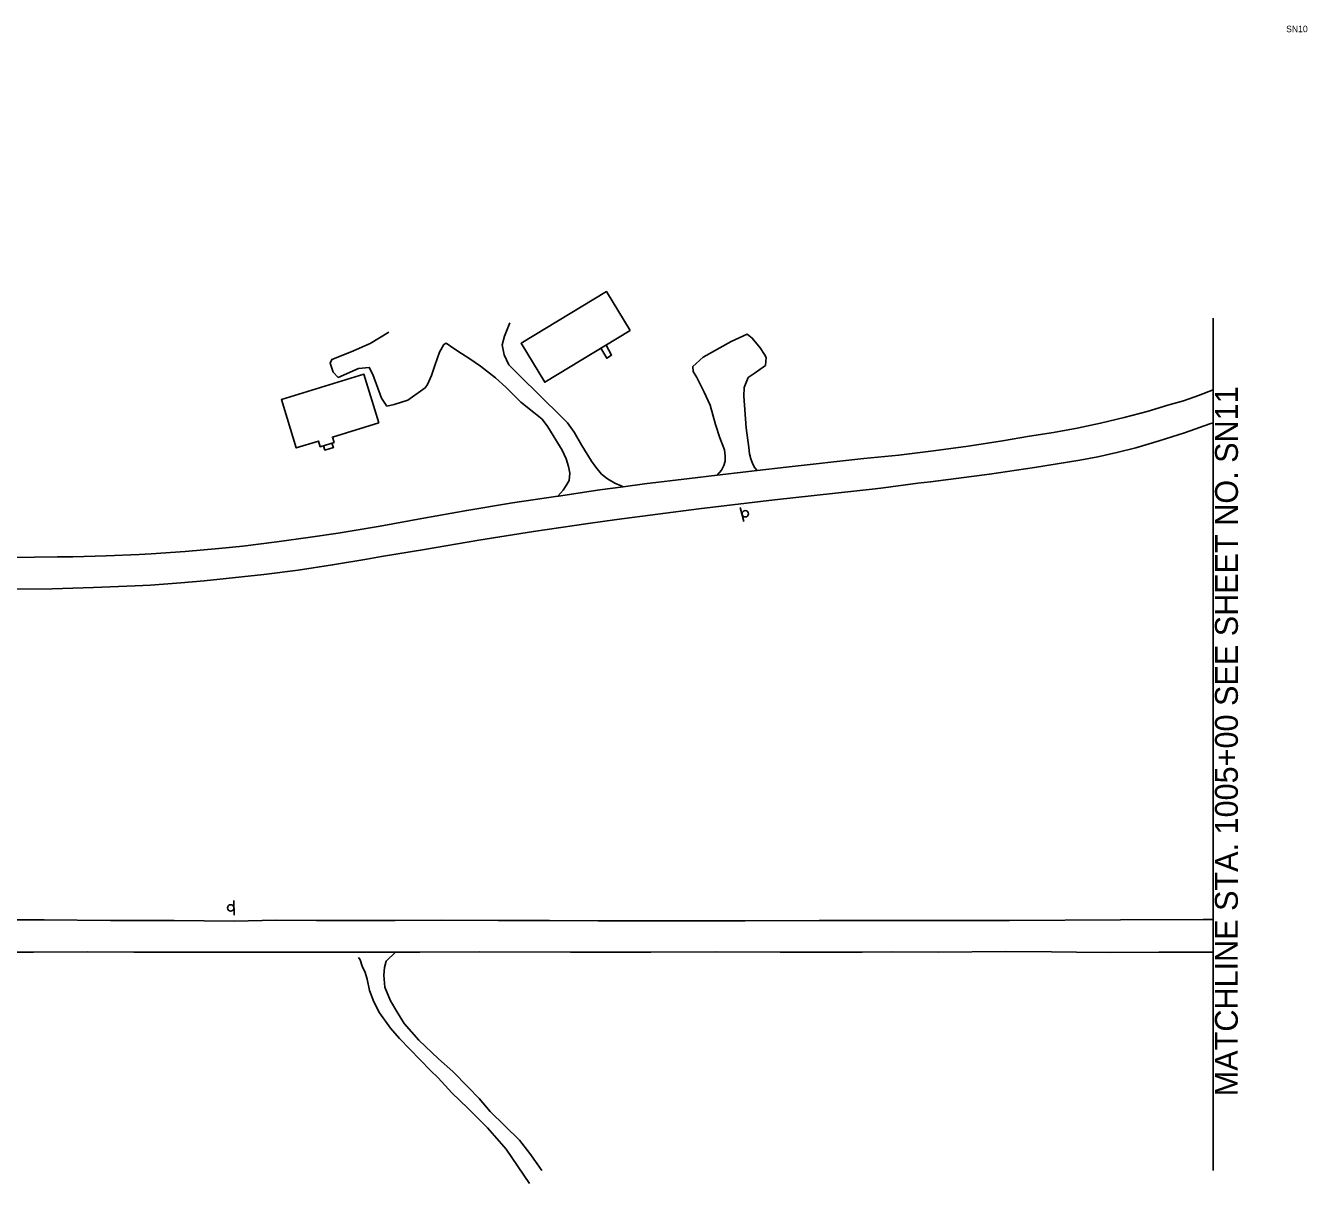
# Model space of a CAD drawing. Extents: x 1738744 to 1740332, y 1166701 to 1167640.
# Drawn here: x 1739538 to 1740332, y 1166923 to 1167640 of the extents above; entities that cross this region are included whole.
import ezdxf

# ---------------------------------------------------------------- set-up
doc = ezdxf.new("R2010")
doc.units = 0
for name, color, linetype in [('RD_EX_Bldg', 7, 'Continuous'), ('RD_EX_Conc', 7, 'Continuous'), ('RD_EX_Driveway', 7, 'Continuous'), ('RD_EX_Road', 7, 'Continuous'), ('RD_SHT_MatchLine', 7, 'Continuous'), ('RD_SHT_TX', 7, 'Continuous'), ('SN_P_Signs', 7, 'Continuous')]:
    doc.layers.add(name, color=color, linetype=linetype)

msp = doc.modelspace()

# ---------------------------------------------------------------- linework, layer by layer
at = {"layer": 'RD_EX_Bldg'}
for points in [[(1739912.39, 1167451.15), (1739859.57, 1167419.12), (1739844.91, 1167443.29), (1739897.73, 1167475.33), (1739912.39, 1167451.15)], [(1739756.77, 1167394.05), (1739728.03, 1167385.22), (1739729.06, 1167381.89), (1739720.43, 1167379.24), (1739719.36, 1167382.74), (1739705.63, 1167378.52), (1739696.44, 1167408.4), (1739747.54, 1167424.1), (1739756.77, 1167394.05)]]:
    msp.add_lwpolyline(points, dxfattribs=at)
at = {"layer": 'RD_EX_Conc'}
for points in [[(1739894.32, 1167440.19), (1739898.02, 1167434.04), (1739901.02, 1167435.97), (1739897.54, 1167442.15)], [(1739722.39, 1167379.84), (1739723.36, 1167377.15), (1739728.58, 1167378.66), (1739727.64, 1167381.46)]]:
    msp.add_lwpolyline(points, dxfattribs=at)
at = {"layer": 'RD_EX_Driveway'}
for points in [[(1739837.98, 1167455.88), (1739834.56, 1167447.68), (1739833.18, 1167442.29), (1739834.41, 1167436.06), (1739837.4, 1167429.92), (1739843.74, 1167423.51), (1739869.98, 1167397.75), (1739873.63, 1167394.01), (1739877.82, 1167388.32), (1739882.61, 1167380.05), (1739888.56, 1167370.34), (1739891.27, 1167366.58), (1739894.75, 1167362.26), (1739898.52, 1167359.41), (1739903.05, 1167356.63), (1739906.87, 1167354.91), (1739908.14, 1167354.47)], [(1739867.57, 1167348.61), (1739870.95, 1167352.23), (1739872.81, 1167355.23), (1739874.66, 1167358.23), (1739875.04, 1167362.86), (1739874.28, 1167366.96), (1739872.89, 1167371.75), (1739870.29, 1167377.02), (1739861.43, 1167391.49), (1739857.89, 1167396.24), (1739852.78, 1167400.52), (1739844.8, 1167406.78), (1739835.45, 1167416.12), (1739829.12, 1167421.9), (1739819.68, 1167429.08), (1739813.11, 1167433.6), (1739808.08, 1167436.93), (1739803.3, 1167440.02), (1739798.46, 1167443.29), (1739797.06, 1167442.54), (1739794.25, 1167437.84), (1739791.56, 1167429.47), (1739789.38, 1167423.38), (1739786.82, 1167417.8), (1739785.55, 1167415.77), (1739774.74, 1167408.06), (1739766.35, 1167405.29), (1739761.78, 1167404.42), (1739758.49, 1167409.25), (1739752.95, 1167424), (1739750.8, 1167428.32), (1739744.2, 1167427.58), (1739731.49, 1167422.16), (1739728.45, 1167425.34), (1739726.69, 1167431.06), (1739727.59, 1167433.21), (1739739.66, 1167438), (1739751.35, 1167443.17), (1739763.04, 1167450.24)], [(1739966.49, 1167361.63), (1739969.12, 1167364.77), (1739970.54, 1167367.51), (1739971.26, 1167370.19), (1739971.4, 1167373.67), (1739970.91, 1167377.27), (1739968.08, 1167384.7), (1739965.37, 1167392.89), (1739962.04, 1167404.86), (1739958.39, 1167412.97), (1739953.7, 1167422.14), (1739951.5, 1167425.9), (1739951.27, 1167428.87), (1739957.76, 1167434.72), (1739975.13, 1167444.4), (1739984.93, 1167448.9), (1739988.12, 1167446.55), (1739993.07, 1167440.42), (1739995.66, 1167436.29), (1739996.7, 1167434.53), (1739996.33, 1167429.59), (1739989.31, 1167424.68), (1739985.62, 1167422.09), (1739983.12, 1167415.86), (1739982.82, 1167410.48), (1739984.36, 1167391.01), (1739985.92, 1167378.68), (1739986.48, 1167374.89), (1739987.23, 1167371.67), (1739988.41, 1167368.45), (1739989.84, 1167366.07), (1739991.11, 1167364.46)], [(1739850.15, 1166922.92), (1739835.71, 1166944.13), (1739824.1, 1166957.32), (1739819.1, 1166962.31), (1739811.87, 1166969.47), (1739802, 1166979.06), (1739793.44, 1166988.28), (1739788.84, 1166992.75), (1739769.63, 1167012.7), (1739763.97, 1167019.1), (1739757.1, 1167028.59), (1739753.76, 1167035.41), (1739750.95, 1167042.37), (1739749.55, 1167049.34), (1739748.2, 1167053.46), (1739746.46, 1167057.45), (1739745.12, 1167061.31), (1739744.06, 1167062.85)], [(1739767.09, 1167066.1), (1739761.36, 1167060.47), (1739760.25, 1167056.7), (1739759.93, 1167051.78), (1739760.43, 1167044.53), (1739764.04, 1167036.04), (1739767.89, 1167029.36), (1739772.53, 1167021.91), (1739781.48, 1167011.67), (1739793.7, 1167000.05), (1739802.62, 1166992.15), (1739812.09, 1166982.56), (1739818.93, 1166975.53), (1739825.79, 1166967.45), (1739843.94, 1166949.69), (1739850.28, 1166941.35), (1739854.91, 1166934.93), (1739857.69, 1166930.82)]]:
    msp.add_lwpolyline(points, dxfattribs=at)
at = {"layer": 'RD_EX_Road'}
for points in [[(1740273.73, 1167414.36), (1740264.74, 1167410.91), (1740255.3, 1167407.7), (1740245.74, 1167404.87), (1740232.92, 1167401.11), (1740218.51, 1167397.27), (1740203.99, 1167393.81), (1740189.39, 1167390.74), (1740174.72, 1167388.05), (1740159.98, 1167385.76), (1740143.21, 1167382.88), (1740121.82, 1167379.56), (1740100.38, 1167376.63), (1740078.88, 1167374.09), (1740057.34, 1167371.94), (1740009.16, 1167366.54), (1739991.11, 1167364.46), (1739966.49, 1167361.63), (1739949.17, 1167359.63), (1739921.45, 1167356.28), (1739908.14, 1167354.47), (1739893.77, 1167352.53), (1739868, 1167348.68), (1739867.57, 1167348.61), (1739839.61, 1167344.42), (1739811.27, 1167339.77), (1739783.49, 1167334.82), (1739757.57, 1167330.1), (1739731.59, 1167325.76), (1739714.42, 1167323.12), (1739693.48, 1167320.22), (1739672.49, 1167317.72), (1739657.66, 1167316.2), (1739636.67, 1167314.33), (1739615.66, 1167312.86), (1739608.35, 1167312.44), (1739587.72, 1167311.56), (1739567.09, 1167311.08), (1739557.71, 1167310.99), (1739543.45, 1167310.78), (1739529.2, 1167310.56)], [(1740273.73, 1167394.07), (1740271.68, 1167393.32), (1740271.6, 1167393.3), (1740255.95, 1167387.86), (1740240.17, 1167382.8), (1740225.71, 1167378.53), (1740214.06, 1167375.58), (1740202.33, 1167373.01), (1740191.05, 1167370.92), (1740163.06, 1167366.35), (1740135.2, 1167362.2), (1740098.65, 1167357.57), (1740090.75, 1167356.62), (1740069.55, 1167353.8), (1740064.27, 1167353.04), (1740002.01, 1167346.23), (1739955.07, 1167340.72), (1739904.17, 1167334.13), (1739886.42, 1167331.69), (1739852.57, 1167326.72), (1739818.77, 1167321.37), (1739785.03, 1167315.62), (1739758.44, 1167311.24), (1739749.28, 1167309.58), (1739728.11, 1167306.01), (1739706.87, 1167302.83), (1739685.57, 1167300.04), (1739648.63, 1167296.13), (1739634.03, 1167294.84), (1739615.24, 1167293.54), (1739605.69, 1167293.03), (1739580.02, 1167291.93), (1739554.34, 1167291.23), (1739528.65, 1167290.91)], [(1740273.73, 1167086.27), (1740267.63, 1167086.27), (1740216.38, 1167086.1), (1740147.52, 1167085.79), (1740062.73, 1167085.66), (1740029.61, 1167085.81), (1739983.83, 1167085.45), (1739933.29, 1167085.54), (1739892.69, 1167085.59), (1739862.49, 1167085.65), (1739830.79, 1167085.7), (1739795.84, 1167086.02), (1739766.87, 1167085.72), (1739718.2, 1167085.79), (1739693.11, 1167085.86), (1739667.04, 1167085.42), (1739629.98, 1167085.72), (1739590.58, 1167085.84), (1739549.43, 1167086.09), (1739465.49, 1167086.14)], [(1739501.43, 1167066.1), (1739542.74, 1167066.04), (1739576.22, 1167066.27), (1739604.92, 1167066.12), (1739627.53, 1167066.05), (1739670.74, 1167066.12), (1739716.18, 1167066.12), (1739738.96, 1167066.12), (1739759.48, 1167066.12), (1739767.09, 1167066.1), (1739782.15, 1167066.07), (1739819.26, 1167066.29), (1739875.47, 1167066.16), (1739925.31, 1167066.19), (1739966.18, 1167066.28), (1740005.36, 1167066.21), (1740056.31, 1167066.13), (1740074.3, 1167066.28), (1740103.39, 1167066.21), (1740145.24, 1167066.48), (1740173.63, 1167066.38), (1740189.13, 1167066.16), (1740210.32, 1167065.87), (1740239.97, 1167066.14), (1740248.88, 1167066.16), (1740269.89, 1167066.22), (1740273.73, 1167066.22)]]:
    msp.add_lwpolyline(points, dxfattribs=at)
at = {"layer": 'RD_SHT_MatchLine'}
msp.add_lwpolyline([(1740273.73, 1166930.89), (1740273.73, 1167194.04), (1740273.73, 1167458.8)], dxfattribs=at)
at = {"layer": 'SN_P_Signs'}
for p, q in [((1739980.7, 1167341.56), (1739983.02, 1167332.86)), ((1739667.05, 1167089.03), (1739666.95, 1167098.03))]:
    msp.add_line(p, q, dxfattribs=at)
for centre in [(1739983.82, 1167337.71), (1739664.98, 1167093.52)]:
    msp.add_circle(centre, 2, dxfattribs=at)

# ---------------------------------------------------------------- texts
at = {"layer": 'RD_SHT_TX'}
msp.add_text('SN10', height=4, dxfattribs=at).set_placement((1740318.92, 1167636))
msp.add_text('MATCHLINE STA. 1005+00 SEE SHEET NO. SN11', height=14.1726, rotation=89.98556, dxfattribs=at).set_placement((1740288.98, 1166976.88))

doc.saveas('drawing.dxf')
